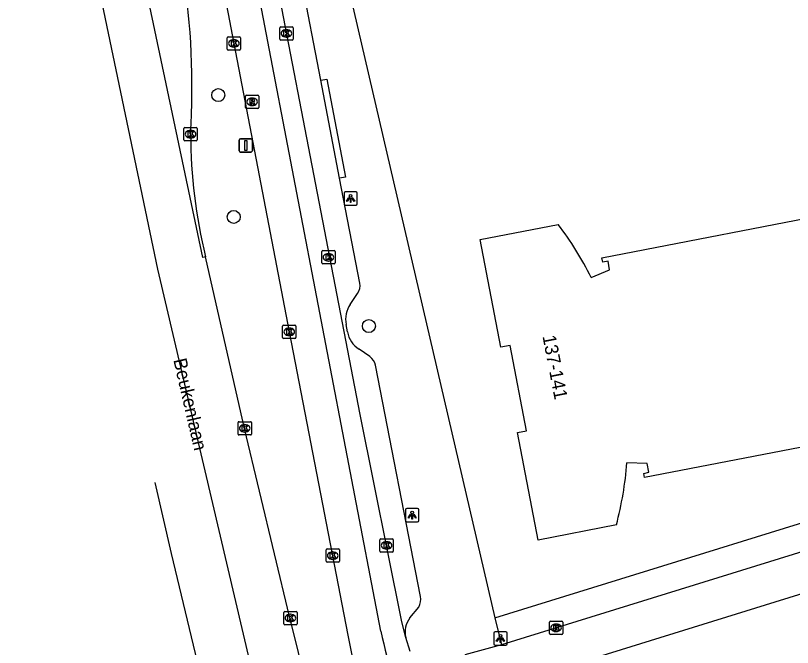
# Model space of a CAD drawing. Extents: x 159265 to 160143, y 383413 to 384319.
# Drawn here: x 159315.5 to 159373.8, y 383673 to 383720.5 of the extents above; entities that cross this region are included whole.
import ezdxf

# ---------------------------------------------------------------- set-up
doc = ezdxf.new("R2010")
doc.units = 0
for name, color, linetype in [('IMGEO_Boom', 7, 'Continuous'), ('IMGEO_Fietspad_open', 7, 'Continuous'), ('IMGEO_Kolk', 7, 'Continuous'), ('IMGEO_Lichtpunt', 7, 'Continuous'), ('IMGEO_Openbare_ruimte_label', 7, 'Continuous'), ('IMGEO_Pand', 7, 'Continuous'), ('IMGEO_Pand_nummerreeks', 7, 'Continuous'), ('IMGEO_Rijbaan_lokaal_gesloten', 7, 'Continuous'), ('IMGEO_Rijbaan_lokaal_open', 7, 'Continuous'), ('IMGEO_Rijbaan_regionaal_gesloten', 7, 'Continuous'), ('IMGEO_Rioolput', 7, 'Continuous'), ('IMGEO_Verkeersbordpaal', 7, 'Continuous'), ('IMGEO_Voetpad_open', 7, 'Continuous')]:
    doc.layers.add(name, color=color, linetype=linetype)

msp = doc.modelspace()

# ---------------------------------------------------------------- linework, layer by layer
at = {"layer": 'IMGEO_Boom'}
for centre in [(159330.686, 383714.482), (159331.842, 383705.329), (159341.988, 383697.137)]:
    msp.add_circle(centre, 0.489, dxfattribs=at)
at = {"layer": 'IMGEO_Fietspad_open'}
for points in [[(159404.099, 383686.209), (159349.78, 383669.374)], [(159387.244, 383684.145), (159351.932, 383673.197)], [(159351.932, 383673.197), (159349.189, 383672.436)]]:
    msp.add_lwpolyline(points, dxfattribs=at)
at = {"layer": 'IMGEO_Kolk'}
for p, q in [((159335.37, 383719.615), (159336.222, 383719.615)), ((159335.295, 383718.689), (159335.295, 383719.541)), ((159335.783, 383719.395), (159335.808, 383719.395)), ((159336.296, 383719.541), (159336.296, 383718.689)), ((159331.354, 383717.939), (159331.354, 383718.791)), ((159331.429, 383718.865), (159332.281, 383718.865)), ((159331.842, 383718.645), (159331.867, 383718.645)), ((159332.355, 383718.791), (159332.355, 383717.939)), ((159336.222, 383718.615), (159335.37, 383718.615)), ((159335.806, 383718.835), (159335.781, 383718.835)), ((159332.281, 383717.865), (159331.429, 383717.865)), ((159331.865, 383718.085), (159331.84, 383718.085)), ((159328.107, 383711.122), (159328.107, 383711.974)), ((159328.182, 383712.048), (159329.034, 383712.048)), ((159329.108, 383711.974), (159329.108, 383711.122)), ((159328.595, 383711.828), (159328.62, 383711.828)), ((159329.034, 383711.048), (159328.182, 383711.048)), ((159328.618, 383711.268), (159328.593, 383711.268)), ((159338.456, 383701.875), (159338.456, 383702.727)), ((159338.531, 383702.801), (159339.383, 383702.801)), ((159339.457, 383702.727), (159339.457, 383701.875)), ((159338.944, 383702.581), (159338.969, 383702.581)), ((159339.383, 383701.801), (159338.531, 383701.801)), ((159338.967, 383702.021), (159338.942, 383702.021)), ((159335.515, 383696.277), (159335.515, 383697.129)), ((159335.59, 383697.203), (159336.442, 383697.203)), ((159336.003, 383696.983), (159336.028, 383696.983)), ((159336.516, 383697.129), (159336.516, 383696.277)), ((159336.026, 383696.423), (159336.001, 383696.423)), ((159336.442, 383696.203), (159335.59, 383696.203)), ((159332.165, 383689.029), (159332.165, 383689.881)), ((159332.24, 383689.955), (159333.092, 383689.955)), ((159333.166, 383689.881), (159333.166, 383689.029)), ((159332.653, 383689.735), (159332.678, 383689.735)), ((159333.092, 383688.955), (159332.24, 383688.955)), ((159332.676, 383689.175), (159332.651, 383689.175)), ((159342.821, 383680.238), (159342.821, 383681.09)), ((159342.896, 383681.164), (159343.748, 383681.164)), ((159343.822, 383681.09), (159343.822, 383680.238)), ((159343.309, 383680.944), (159343.334, 383680.944)), ((159338.773, 383679.469), (159338.773, 383680.321)), ((159338.848, 383680.395), (159339.7, 383680.395)), ((159339.261, 383680.175), (159339.286, 383680.175)), ((159339.774, 383680.321), (159339.774, 383679.469)), ((159343.748, 383680.164), (159342.896, 383680.164)), ((159343.332, 383680.384), (159343.307, 383680.384)), ((159339.7, 383679.395), (159338.848, 383679.395)), ((159339.284, 383679.615), (159339.259, 383679.615)), ((159335.595, 383674.782), (159335.595, 383675.634)), ((159335.67, 383675.708), (159336.522, 383675.708)), ((159336.083, 383675.488), (159336.108, 383675.488)), ((159336.596, 383675.634), (159336.596, 383674.782)), ((159336.522, 383674.708), (159335.67, 383674.708)), ((159336.106, 383674.928), (159336.081, 383674.928)), ((159355.544, 383674.052), (159355.544, 383674.904)), ((159355.619, 383674.978), (159356.471, 383674.978)), ((159356.032, 383674.758), (159356.057, 383674.758)), ((159356.545, 383674.904), (159356.545, 383674.052)), ((159356.055, 383674.198), (159356.03, 383674.198)), ((159356.471, 383673.978), (159355.619, 383673.978))]:
    msp.add_line(p, q, dxfattribs=at)
for points in [[(159335.37, 383719.615), (159336.222, 383719.615)], [(159335.295, 383718.689), (159335.295, 383719.541)], [(159335.616, 383719.315), (159335.739, 383719.315), (159335.739, 383719.164), (159335.869, 383719.315), (159336.033, 383719.315), (159335.887, 383719.164), (159336.04, 383718.915), (159335.888, 383718.915), (159335.803, 383719.079), (159335.739, 383719.012), (159335.739, 383718.915), (159335.616, 383718.915), (159335.616, 383719.315)], [(159336.296, 383719.541), (159336.296, 383718.689)], [(159331.354, 383717.939), (159331.354, 383718.791)], [(159331.429, 383718.865), (159332.281, 383718.865)], [(159331.675, 383718.565), (159331.798, 383718.565), (159331.798, 383718.414), (159331.928, 383718.565), (159332.092, 383718.565), (159331.946, 383718.414), (159332.099, 383718.165), (159331.947, 383718.165), (159331.862, 383718.329), (159331.798, 383718.262), (159331.798, 383718.165), (159331.675, 383718.165), (159331.675, 383718.565)], [(159332.355, 383718.791), (159332.355, 383717.939)], [(159336.222, 383718.615), (159335.37, 383718.615)], [(159332.281, 383717.865), (159331.429, 383717.865)], [(159328.107, 383711.122), (159328.107, 383711.974)], [(159328.182, 383712.048), (159329.034, 383712.048)], [(159329.108, 383711.974), (159329.108, 383711.122)], [(159328.428, 383711.748), (159328.551, 383711.748), (159328.551, 383711.597), (159328.681, 383711.748), (159328.845, 383711.748), (159328.699, 383711.597), (159328.852, 383711.348), (159328.7, 383711.348), (159328.615, 383711.512), (159328.551, 383711.445), (159328.551, 383711.348), (159328.428, 383711.348), (159328.428, 383711.748)], [(159329.034, 383711.048), (159328.182, 383711.048)], [(159338.456, 383701.875), (159338.456, 383702.727)], [(159338.531, 383702.801), (159339.383, 383702.801)], [(159339.457, 383702.727), (159339.457, 383701.875)], [(159338.777, 383702.501), (159338.9, 383702.501), (159338.9, 383702.35), (159339.03, 383702.501), (159339.194, 383702.501), (159339.048, 383702.35), (159339.201, 383702.101), (159339.049, 383702.101), (159338.964, 383702.265), (159338.9, 383702.198), (159338.9, 383702.101), (159338.777, 383702.101), (159338.777, 383702.501)], [(159339.383, 383701.801), (159338.531, 383701.801)], [(159335.515, 383696.277), (159335.515, 383697.129)], [(159335.59, 383697.203), (159336.442, 383697.203)], [(159335.836, 383696.903), (159335.959, 383696.903), (159335.959, 383696.752), (159336.089, 383696.903), (159336.253, 383696.903), (159336.107, 383696.752), (159336.26, 383696.503), (159336.108, 383696.503), (159336.023, 383696.667), (159335.959, 383696.6), (159335.959, 383696.503), (159335.836, 383696.503), (159335.836, 383696.903)], [(159336.516, 383697.129), (159336.516, 383696.277)], [(159336.442, 383696.203), (159335.59, 383696.203)], [(159332.165, 383689.029), (159332.165, 383689.881)], [(159332.24, 383689.955), (159333.092, 383689.955)], [(159333.166, 383689.881), (159333.166, 383689.029)], [(159332.486, 383689.655), (159332.609, 383689.655), (159332.609, 383689.504), (159332.739, 383689.655), (159332.903, 383689.655), (159332.757, 383689.504), (159332.91, 383689.255), (159332.758, 383689.255), (159332.673, 383689.419), (159332.609, 383689.352), (159332.609, 383689.255), (159332.486, 383689.255), (159332.486, 383689.655)], [(159333.092, 383688.955), (159332.24, 383688.955)], [(159342.821, 383680.238), (159342.821, 383681.09)], [(159342.896, 383681.164), (159343.748, 383681.164)], [(159343.822, 383681.09), (159343.822, 383680.238)], [(159343.142, 383680.864), (159343.265, 383680.864), (159343.265, 383680.713), (159343.395, 383680.864), (159343.559, 383680.864), (159343.413, 383680.713), (159343.566, 383680.464), (159343.414, 383680.464), (159343.329, 383680.628), (159343.265, 383680.561), (159343.265, 383680.464), (159343.142, 383680.464), (159343.142, 383680.864)], [(159338.773, 383679.469), (159338.773, 383680.321)], [(159338.848, 383680.395), (159339.7, 383680.395)], [(159339.094, 383680.095), (159339.217, 383680.095), (159339.217, 383679.944), (159339.347, 383680.095), (159339.511, 383680.095), (159339.365, 383679.944), (159339.518, 383679.695), (159339.366, 383679.695), (159339.281, 383679.859), (159339.217, 383679.792), (159339.217, 383679.695), (159339.094, 383679.695), (159339.094, 383680.095)], [(159339.774, 383680.321), (159339.774, 383679.469)], [(159343.748, 383680.164), (159342.896, 383680.164)], [(159339.7, 383679.395), (159338.848, 383679.395)], [(159335.595, 383674.782), (159335.595, 383675.634)], [(159335.67, 383675.708), (159336.522, 383675.708)], [(159335.916, 383675.408), (159336.039, 383675.408), (159336.039, 383675.257), (159336.169, 383675.408), (159336.333, 383675.408), (159336.187, 383675.257), (159336.34, 383675.008), (159336.188, 383675.008), (159336.103, 383675.172), (159336.039, 383675.105), (159336.039, 383675.008), (159335.916, 383675.008), (159335.916, 383675.408)], [(159336.596, 383675.634), (159336.596, 383674.782)], [(159336.522, 383674.708), (159335.67, 383674.708)], [(159355.544, 383674.052), (159355.544, 383674.904)], [(159355.619, 383674.978), (159356.471, 383674.978)], [(159355.865, 383674.678), (159355.988, 383674.678), (159355.988, 383674.527), (159356.118, 383674.678), (159356.282, 383674.678), (159356.136, 383674.527), (159356.289, 383674.278), (159356.137, 383674.278), (159356.052, 383674.442), (159355.988, 383674.375), (159355.988, 383674.278), (159355.865, 383674.278), (159355.865, 383674.678)], [(159356.545, 383674.904), (159356.545, 383674.052)], [(159356.471, 383673.978), (159355.619, 383673.978)]]:
    msp.add_lwpolyline(points, dxfattribs=at)
for centre, start, end in [((159335.372, 383719.539), 91.55205, 178.44795), ((159335.372, 383719.539), 91.55205, 178.44795), ((159336.22, 383719.539), 1.55205, 88.44795), ((159336.22, 383719.539), 1.55205, 88.44795), ((159331.431, 383718.789), 91.55205, 178.44795), ((159331.431, 383718.789), 91.55205, 178.44795), ((159332.279, 383718.789), 1.55205, 88.44795), ((159332.279, 383718.789), 1.55205, 88.44795), ((159335.372, 383718.691), 181.55205, 268.44795), ((159335.372, 383718.691), 181.55205, 268.44795), ((159336.22, 383718.691), 271.55205, 358.44795), ((159336.22, 383718.691), 271.55205, 358.44795), ((159331.431, 383717.941), 181.55205, 268.44795), ((159331.431, 383717.941), 181.55205, 268.44795), ((159332.279, 383717.941), 271.55205, 358.44795), ((159332.279, 383717.941), 271.55205, 358.44795), ((159328.184, 383711.972), 91.55205, 178.44795), ((159328.184, 383711.972), 91.55205, 178.44795), ((159329.032, 383711.972), 1.55205, 88.44795), ((159329.032, 383711.972), 1.55205, 88.44795), ((159328.184, 383711.124), 181.55205, 268.44795), ((159328.184, 383711.124), 181.55205, 268.44795), ((159329.032, 383711.124), 271.55205, 358.44795), ((159329.032, 383711.124), 271.55205, 358.44795), ((159338.533, 383702.725), 91.55205, 178.44795), ((159338.533, 383702.725), 91.55205, 178.44795), ((159339.381, 383702.725), 1.55205, 88.44795), ((159339.381, 383702.725), 1.55205, 88.44795), ((159338.533, 383701.877), 181.55205, 268.44795), ((159338.533, 383701.877), 181.55205, 268.44795), ((159339.381, 383701.877), 271.55205, 358.44795), ((159339.381, 383701.877), 271.55205, 358.44795), ((159335.592, 383697.127), 91.55205, 178.44795), ((159335.592, 383697.127), 91.55205, 178.44795), ((159336.44, 383697.127), 1.55205, 88.44795), ((159336.44, 383697.127), 1.55205, 88.44795), ((159335.592, 383696.279), 181.55205, 268.44795), ((159335.592, 383696.279), 181.55205, 268.44795), ((159336.44, 383696.279), 271.55205, 358.44795), ((159336.44, 383696.279), 271.55205, 358.44795), ((159332.242, 383689.879), 91.55205, 178.44795), ((159332.242, 383689.879), 91.55205, 178.44795), ((159333.09, 383689.879), 1.55205, 88.44795), ((159333.09, 383689.879), 1.55205, 88.44795), ((159332.242, 383689.031), 181.55205, 268.44795), ((159332.242, 383689.031), 181.55205, 268.44795), ((159333.09, 383689.031), 271.55205, 358.44795), ((159333.09, 383689.031), 271.55205, 358.44795), ((159342.898, 383681.088), 91.55205, 178.44795), ((159342.898, 383681.088), 91.55205, 178.44795), ((159343.746, 383681.088), 1.55205, 88.44795), ((159343.746, 383681.088), 1.55205, 88.44795), ((159338.85, 383680.319), 91.55205, 178.44795), ((159338.85, 383680.319), 91.55205, 178.44795), ((159339.698, 383680.319), 1.55205, 88.44795), ((159339.698, 383680.319), 1.55205, 88.44795), ((159342.898, 383680.24), 181.55205, 268.44795), ((159342.898, 383680.24), 181.55205, 268.44795), ((159343.746, 383680.24), 271.55205, 358.44795), ((159343.746, 383680.24), 271.55205, 358.44795), ((159338.85, 383679.471), 181.55205, 268.44795), ((159338.85, 383679.471), 181.55205, 268.44795), ((159339.698, 383679.471), 271.55205, 358.44795), ((159339.698, 383679.471), 271.55205, 358.44795), ((159335.672, 383675.632), 91.55205, 178.44795), ((159335.672, 383675.632), 91.55205, 178.44795), ((159336.52, 383675.632), 1.55205, 88.44795), ((159336.52, 383675.632), 1.55205, 88.44795), ((159335.672, 383674.784), 181.55205, 268.44795), ((159335.672, 383674.784), 181.55205, 268.44795), ((159336.52, 383674.784), 271.55205, 358.44795), ((159336.52, 383674.784), 271.55205, 358.44795), ((159355.621, 383674.902), 91.55205, 178.44795), ((159355.621, 383674.902), 91.55205, 178.44795), ((159356.469, 383674.902), 1.55205, 88.44795), ((159356.469, 383674.902), 1.55205, 88.44795), ((159355.621, 383674.054), 181.55205, 268.44795), ((159355.621, 383674.054), 181.55205, 268.44795), ((159356.469, 383674.054), 271.55205, 358.44795), ((159356.469, 383674.054), 271.55205, 358.44795)]:
    msp.add_arc(centre, 0.0765, start, end, dxfattribs=at)
for centre, major_axis, ratio, start_param, end_param in [((159335.782, 383719.115), (-0.387, 0.002), 0.722429, 4.712389, 7.853982), ((159335.807, 383719.115), (-0.39, 0.002), 0.717154, 1.570796, 4.712389), ((159331.841, 383718.365), (-0.387, 0.002), 0.722429, 4.712389, 7.853982), ((159331.866, 383718.365), (-0.39, 0.002), 0.717154, 1.570796, 4.712389), ((159328.594, 383711.548), (-0.387, 0.002), 0.722429, 4.712389, 7.853982), ((159328.619, 383711.548), (-0.39, 0.002), 0.717154, 1.570796, 4.712389), ((159338.943, 383702.301), (-0.387, 0.002), 0.722429, 4.712389, 7.853982), ((159338.968, 383702.301), (-0.39, 0.002), 0.717154, 1.570796, 4.712389), ((159336.002, 383696.703), (-0.387, 0.002), 0.722429, 4.712389, 7.853982), ((159336.027, 383696.703), (-0.39, 0.002), 0.717154, 1.570796, 4.712389), ((159332.652, 383689.455), (-0.387, 0.002), 0.722429, 4.712389, 7.853982), ((159332.677, 383689.455), (-0.39, 0.002), 0.717154, 1.570796, 4.712389), ((159343.308, 383680.664), (-0.387, 0.002), 0.722429, 4.712389, 7.853982), ((159343.333, 383680.664), (-0.39, 0.002), 0.717154, 1.570796, 4.712389), ((159339.26, 383679.895), (-0.387, 0.002), 0.722429, 4.712389, 7.853982), ((159339.285, 383679.895), (-0.39, 0.002), 0.717154, 1.570796, 4.712389), ((159336.082, 383675.208), (-0.387, 0.002), 0.722429, 4.712389, 7.853982), ((159336.107, 383675.208), (-0.39, 0.002), 0.717154, 1.570796, 4.712389), ((159356.031, 383674.478), (-0.387, 0.002), 0.722429, 4.712389, 7.853982), ((159356.056, 383674.478), (-0.39, 0.002), 0.717154, 1.570796, 4.712389)]:
    msp.add_ellipse(centre, major_axis=major_axis, ratio=ratio, start_param=start_param, end_param=end_param, dxfattribs=at)
at = {"layer": 'IMGEO_Lichtpunt'}
for p, q in [((159340.122, 383707.123), (159340.122, 383706.316)), ((159340.122, 383707.123), (159340.122, 383706.316)), ((159341.024, 383707.218), (159340.216, 383707.218)), ((159341.024, 383707.218), (159340.216, 383707.218)), ((159341.118, 383706.316), (159341.118, 383707.123)), ((159341.118, 383706.316), (159341.118, 383707.123)), ((159340.216, 383706.222), (159341.024, 383706.222)), ((159340.216, 383706.222), (159341.024, 383706.222)), ((159345.641, 383683.431), (159344.833, 383683.431)), ((159345.641, 383683.431), (159344.833, 383683.431)), ((159344.739, 383683.336), (159344.739, 383682.529)), ((159344.739, 383683.336), (159344.739, 383682.529)), ((159345.735, 383682.529), (159345.735, 383683.336)), ((159345.735, 383682.529), (159345.735, 383683.336)), ((159344.833, 383682.435), (159345.641, 383682.435)), ((159344.833, 383682.435), (159345.641, 383682.435)), ((159351.365, 383674.071), (159351.365, 383673.264)), ((159351.365, 383674.071), (159351.365, 383673.264)), ((159352.267, 383674.166), (159351.459, 383674.166)), ((159352.267, 383674.166), (159351.459, 383674.166)), ((159352.361, 383673.264), (159352.361, 383674.071)), ((159352.361, 383673.264), (159352.361, 383674.071)), ((159351.459, 383673.17), (159352.267, 383673.17)), ((159351.459, 383673.17), (159352.267, 383673.17))]:
    msp.add_line(p, q, dxfattribs=at)
for points in [[(159340.496, 383706.787), (159340.535, 383706.759), (159340.347, 383706.497), (159340.309, 383706.524), (159340.496, 383706.787)], [(159340.598, 383706.739), (159340.645, 383706.739), (159340.645, 383706.417), (159340.598, 383706.417), (159340.598, 383706.739)], [(159340.708, 383706.759), (159340.746, 383706.786), (159340.933, 383706.524), (159340.894, 383706.496), (159340.708, 383706.759)], [(159345.113, 383683), (159345.152, 383682.972), (159344.964, 383682.71), (159344.926, 383682.737), (159345.113, 383683)], [(159345.215, 383682.952), (159345.262, 383682.952), (159345.262, 383682.63), (159345.215, 383682.63), (159345.215, 383682.952)], [(159345.325, 383682.972), (159345.363, 383682.999), (159345.55, 383682.737), (159345.511, 383682.709), (159345.325, 383682.972)], [(159351.739, 383673.735), (159351.778, 383673.707), (159351.59, 383673.445), (159351.552, 383673.472), (159351.739, 383673.735)], [(159351.841, 383673.687), (159351.888, 383673.687), (159351.888, 383673.365), (159351.841, 383673.365), (159351.841, 383673.687)], [(159351.951, 383673.707), (159351.989, 383673.734), (159352.176, 383673.472), (159352.137, 383673.444), (159351.951, 383673.707)]]:
    msp.add_lwpolyline(points, dxfattribs=at)
for centre in [(159340.621, 383706.921), (159345.238, 383683.134), (159351.864, 383673.869)]:
    msp.add_circle(centre, 0.0994, dxfattribs=at)
for centre, start, end in [((159340.216, 383707.123), 90, 180), ((159340.216, 383707.123), 90, 180), ((159341.024, 383707.123), 0, 90), ((159341.024, 383707.123), 0, 90), ((159340.216, 383706.316), 180, 270), ((159340.216, 383706.316), 180, 270), ((159341.024, 383706.316), 270, 0), ((159341.024, 383706.316), 270, 360), ((159344.833, 383683.336), 90, 180), ((159344.833, 383683.336), 90, 180), ((159345.641, 383683.336), 0, 90), ((159345.641, 383683.336), 0, 90), ((159344.833, 383682.529), 180, 270), ((159344.833, 383682.529), 180, 270), ((159345.641, 383682.529), 270, 0), ((159345.641, 383682.529), 270, 360), ((159351.459, 383674.071), 90, 180), ((159351.459, 383674.071), 90, 180), ((159352.267, 383674.071), 0, 90), ((159352.267, 383674.071), 0, 90), ((159351.459, 383673.264), 180, 270), ((159351.459, 383673.264), 180, 270), ((159352.267, 383673.264), 270, 0), ((159352.267, 383673.264), 270, 360)]:
    msp.add_arc(centre, 0.0946, start, end, dxfattribs=at)
at = {"layer": 'IMGEO_Pand'}
for points in [[(159358.672, 383700.783), (159360.053, 383701.35), (159359.948, 383702), (159359.544, 383701.936), (159359.488, 383702.251), (159378.067, 383705.862), (159379.298, 383699.588), (159380.724, 383699.861), (159381.487, 383695.897), (159380.061, 383695.595), (159381.254, 383689.336), (159362.684, 383685.751), (159362.626, 383686.062), (159362.998, 383686.163), (159362.872, 383686.804), (159361.36, 383686.876)], [(159360.57, 383682.198), (159354.702, 383681.049), (159353.14, 383689.13), (159353.814, 383689.274), (159352.585, 383695.672), (159351.898, 383695.554), (159350.341, 383703.626), (159356.205, 383704.772)]]:
    msp.add_lwpolyline(points, dxfattribs=at)
for centre, radius, start, end in [((159336.012, 383689.527), 25.301, 26.41656, 37.05294), ((159334.976, 383688.926), 26.463, 345.27175, 355.55741)]:
    msp.add_arc(centre, radius, start, end, dxfattribs=at)
at = {"layer": 'IMGEO_Rijbaan_lokaal_gesloten'}
for points in [[(159342.895, 383674.233), (159329.814, 383742.432), (159328.366, 383750), (159327.691, 383753.526), (159326.873, 383757.97), (159323.687, 383778.309)], [(159344.754, 383673.743), (159344.455, 383674.933), (159341.329, 383690.504), (159331.854, 383739.73), (159328.333, 383758.483)], [(159345.1, 383672.695), (159344.754, 383673.743)]]:
    msp.add_lwpolyline(points, dxfattribs=at)
msp.add_arc((159390.161, 383684.084), 48.281, 191.77318, 201.12177, dxfattribs=at)
at = {"layer": 'IMGEO_Rijbaan_lokaal_open'}
msp.add_lwpolyline([(159322.954, 383766.957), (159323.122, 383765.878), (159324.407, 383757.692), (159325.851, 383750), (159328.1, 383738.016), (159331.856, 383718.365), (159336.016, 383696.703), (159339.221, 383679.999), (159340.401, 383673.929), (159342.02, 383665.933), (159342.067, 383665.703), (159342.379, 383664.493)], dxfattribs=at)
at = {"layer": 'IMGEO_Rijbaan_regionaal_gesloten'}
for points in [[(159280.211, 384172.631), (159274.487, 384158.497), (159272.013, 384150.923), (159269.535, 384141.678), (159267.507, 384132.324), (159266.005, 384119.851), (159265.496, 384109.233), (159267.965, 384029.162), (159271.62, 383998.252), (159277.018, 383952.804), (159311.634, 383770.65), (159326.117, 383701.416), (159334.862, 383664.196)], [(159329.732, 383702.333), (159329.536, 383702.291), (159316.548, 383763.855)], [(159338.544, 383665.089), (159336.511, 383673.455), (159336.041, 383675.319), (159332.664, 383689.455), (159329.732, 383702.333)], [(159331.18, 383663.302), (159328.984, 383672.539), (159327.175, 383680.053), (159325.952, 383685.388)]]:
    msp.add_lwpolyline(points, dxfattribs=at)
for centre, radius, start, end in [((159271.004, 383715.018), 57.708, 356.55313, 8.68952), ((159368.428, 383711.733), 39.821, 180.26661, 193.65425)]:
    msp.add_arc(centre, radius, start, end, dxfattribs=at)
at = {"layer": 'IMGEO_Rioolput'}
for p, q in [((159332.721, 383713.555), (159332.721, 383714.407)), ((159332.796, 383714.481), (159333.648, 383714.481)), ((159333.722, 383714.407), (159333.722, 383713.555)), ((159333.209, 383714.261), (159333.234, 383714.261)), ((159333.648, 383713.481), (159332.796, 383713.481)), ((159333.232, 383713.701), (159333.207, 383713.701))]:
    msp.add_line(p, q, dxfattribs=at)
for points in [[(159332.721, 383713.555), (159332.721, 383714.407)], [(159332.796, 383714.481), (159333.648, 383714.481)], [(159333.722, 383714.407), (159333.722, 383713.555)], [(159333.31, 383714.179), (159333.058, 383714.181), (159333.058, 383713.781)], [(159333.058, 383713.781), (159333.182, 383713.781), (159333.182, 383713.943), (159333.193, 383713.943)], [(159333.236, 383714.1), (159333.182, 383714.1), (159333.182, 383714.019)], [(159333.182, 383714.019), (159333.234, 383714.019)], [(159333.24, 383713.914), (159333.311, 383713.781), (159333.451, 383713.781), (159333.386, 383713.907)], [(159333.648, 383713.481), (159332.796, 383713.481)]]:
    msp.add_lwpolyline(points, dxfattribs=at)
for centre, radius, start, end in [((159332.798, 383714.405), 0.0765, 91.55205, 178.44795), ((159332.798, 383714.405), 0.0765, 91.55205, 178.44795), ((159333.646, 383714.405), 0.0765, 1.55205, 88.44795), ((159333.646, 383714.405), 0.0765, 1.55205, 88.44795), ((159333.192, 383713.89), 0.0533, 26.02933, 88.69889), ((159333.218, 383714.208), 0.19, 274.7715, 282.96867), ((159333.242, 383714.004), 0.0964, 77.00612, 93.18647), ((159333.256, 383714.061), 0.0378, 276.66336, 79.67722), ((159333.309, 383714.069), 0.109, 350.36119, 89.41601), ((159333.307, 383714.069), 0.112, 277.58423, 350.98172), ((159333.291, 383713.854), 0.108, 29.51342, 73.79051), ((159332.798, 383713.557), 0.0765, 181.55205, 268.44795), ((159332.798, 383713.557), 0.0765, 181.55205, 268.44795), ((159333.646, 383713.557), 0.0765, 271.55205, 358.44795), ((159333.646, 383713.557), 0.0765, 271.55205, 358.44795)]:
    msp.add_arc(centre, radius, start, end, dxfattribs=at)
for centre, major_axis, ratio, start_param, end_param in [((159333.208, 383713.981), (-0.387, 0.002), 0.722429, 4.712389, 7.853982), ((159333.233, 383713.981), (-0.39, 0.002), 0.717154, 1.570796, 4.712389)]:
    msp.add_ellipse(centre, major_axis=major_axis, ratio=ratio, start_param=start_param, end_param=end_param, dxfattribs=at)
at = {"layer": 'IMGEO_Verkeersbordpaal'}
for p, q in [((159332.253, 383710.304), (159332.253, 383711.104)), ((159332.253, 383711.104), (159332.253, 383710.304)), ((159332.353, 383711.204), (159333.143, 383711.204)), ((159333.143, 383711.204), (159332.353, 383711.204)), ((159333.243, 383711.104), (159333.243, 383710.304)), ((159333.243, 383710.304), (159333.243, 383711.104)), ((159333.143, 383710.204), (159332.353, 383710.204)), ((159332.353, 383710.204), (159333.143, 383710.204))]:
    msp.add_line(p, q, dxfattribs=at)
msp.add_lwpolyline([(159332.673, 383711.079), (159332.823, 383711.079), (159332.823, 383710.329), (159332.673, 383710.329), (159332.673, 383711.079)], dxfattribs=at)
for centre, start, end in [((159332.353, 383711.104), 90, 180), ((159332.353, 383711.104), 90, 180), ((159333.143, 383711.104), 0, 90), ((159333.143, 383711.104), 360, 90), ((159332.353, 383710.304), 180, 270), ((159332.353, 383710.304), 180, 270), ((159333.143, 383710.304), 270, 0), ((159333.143, 383710.304), 270, 0)]:
    msp.add_arc(centre, 0.1, start, end, dxfattribs=at)
at = {"layer": 'IMGEO_Voetpad_open'}
for points in [[(159338.381, 383715.607), (159336.917, 383723.28), (159336.648, 383723.92), (159335.835, 383724.313)], [(159340.609, 383721.889), (159351.446, 383675.234)], [(159338.381, 383715.607), (159338.823, 383715.686), (159340.225, 383708.314), (159339.781, 383708.231)], [(159339.781, 383708.231), (159338.381, 383715.607)], [(159341.304, 383700.358), (159339.781, 383708.231)], [(159340.586, 383698.767), (159341.141, 383699.59)], [(159340.387, 383696.696), (159340.274, 383697.259)], [(159342.07, 383694.838), (159341.252, 383695.401)], [(159345.867, 383676.823), (159342.484, 383694.192)], [(159351.446, 383675.234), (159386.849, 383686.19)], [(159345.061, 383675.213), (159345.727, 383676.031)], [(159351.446, 383675.234), (159351.932, 383673.197)]]:
    msp.add_lwpolyline(points, dxfattribs=at)
for centre, radius, start, end in [((159340.335, 383700.162), 0.988, 324.61646, 11.4183), ((159342.291, 383697.628), 2.051, 146.25862, 190.36264), ((159342.23, 383696.991), 1.867, 189.08787, 238.39431), ((159341.435, 383693.975), 1.072, 11.67841, 53.63052), ((159344.678, 383676.625), 1.206, 330.4892, 9.46182), ((159346.509, 383674.144), 1.8, 143.55305, 192.85434)]:
    msp.add_arc(centre, radius, start, end, dxfattribs=at)

# ---------------------------------------------------------------- texts
at = {"layer": 'IMGEO_Openbare_ruimte_label'}
msp.add_text('Beukenlaan', height=1, rotation=283.0075, dxfattribs=at).set_placement((159327.302, 383694.597))
at = {"layer": 'IMGEO_Pand_nummerreeks'}
msp.add_text('137-141', height=1, rotation=280.87357, dxfattribs=at).set_placement((159355.016, 383696.37))

doc.saveas('drawing.dxf')
